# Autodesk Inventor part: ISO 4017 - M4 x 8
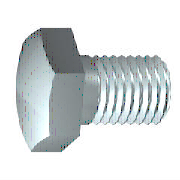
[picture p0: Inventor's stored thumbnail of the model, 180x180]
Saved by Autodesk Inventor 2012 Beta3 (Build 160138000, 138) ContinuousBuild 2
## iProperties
IsCustomPart: 0
Created: 2010-02
Part Number: ISO 4017 - M4 x 8
Material: Stainless Steel, 440C
Description: Hexagon head screws
Document SubType Name: Modeling
Standard: ISO 4017
Designer: Thom Tremblay
Standard Revision: Third edition 1999-08-15
Standards Organization: ISO
Language: en-US
Size Designation: M4 x 8
Categories: <MemberInstance><Categories><Category DisplayName="Fasteners" InternalName="e4da775c-781d-43d5-af7c-5136215cf5a6" Mnemonic="FSTN"><Category DisplayName="Bolts"
Density: 7.75 g/cm^3
Author: Thom Tremblay
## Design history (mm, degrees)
workplane "Work Plane1"
revolve "Body" stored, may be unused: angle "d12" = 90 deg
sketch "Sketch2"
  geometry: L1 (0, 4.041)-(3.5, 2.021); L2 (3.5, 2.021)-(3.5, -2.021); L3 (3.5, -2.021)-(0, -4.041); L4 (0, -4.041)-(-3.5, -2.021); L5 (-3.5, -2.021)-(-3.5, 2.021); L6 (-3.5, 2.021)-(0, 4.041); 2 further points
  constraints: 12 end point, 1 coincident, 1 vertical, 11 other
  dimensions: "d11" = 7 distance between parallel lines of L5 L2 (= SW)
extrude "Head" join sketch "Sketch2" distance "d3" = 2.4 (= KOH - SD); taper "d4" = 0 deg
revolve "Chamfer1" stored, may be unused: angle "d21" = 90 deg
body "Solid1"
feature "Thread" dims "d15" = 5.9 (= GEL), "d16" = 0
chamfer "Chamfer2" distance "d6" = 0.42941 (= -0.5 x SPD + 0.5 x GD); stored, may be unused: second distance "d7" = 0.42952 (computed from GUL), angle "d55" = 45 deg
sketch "Sketch1"
  geometry: L1 (0, 3.015)-(0, 2); L2 (2.1, 2)-(8, 2); L3 (8, 2)-(8, 0); L4 (8, 0)-(-0.4, 0); L5 (-2.08, 0)-(9.68, 0) reference; L6 (-0.4, 0)-(-0.4, 3.015); L7 (-0.4, 3.015)-(0, 3.015); L8 (2.1, 2)-(1.67, 2); L9 (1.67, 2)-(0, 2); L10 (0, -0.603)-(0, 3.618) reference
  constraints: 16 end point, 2 collinear, 2 perpendicular, 1 parallel
  dimensions: "d0" = 8 distance between parallel lines of L3 L1 (= NLG); "d1" = 5.9 distance from line of L2.start L3 (= GEL); "d2" = 4 diameter of L2 L4 (= GD); "d9" = 0.4001 distance between parallel lines of L6 L1 (computed from SD); "d10" = 6.03 diameter of L7 L4 (= SD2); "d13" = 0.42952 distance of L2.start L8.end (computed from GAL); "d14" = 4 diameter of L9 L4 (= BDM)
sketch "Sketch4"
  geometry: L1 (-2.8, 3.5)-(-2.8, 4.041); L2 (-2.8, 4.041)-(-2.487, 4.041); L3 (-2.487, 4.041)-(-2.8, 3.5); L4 (-3.28, 0)-(0.08, 0) reference; L5 (-0.4, 4.041)-(-2.8, 4.041) reference; L6 (-2.8, 2.021)-(-2.8, 4.041) reference
  constraints: 6 end point, 2 collinear, 1 perpendicular, 1 vertical
  dimensions: "d5" = 30 deg angle of L3 L1 (= ANG1); "d19" = 7 diameter of L1.start L4 (= SW0)
other parameters: "NLG" = 8 [user parameter; used in 1 equation term], "GD" = 4 (= NND) [user parameter; used in 2 equation terms], "BDM" = 4 (= NND) [user parameter; used in 1 equation term], "KOH" = 2.8 [user parameter; used in 1 equation term], "GEL" = 5.9 [user parameter; used in 2 equation terms], "SW" = 7 [user parameter; used in 2 equation terms], "SW0" = 7 (= SW) [user parameter; used in 1 equation term], "SPD" = 3.14117 (= NND - 1.2269 x PTC) [user parameter; used in 1 equation term], "SD2" = 6.03 [user parameter; used in 2 equation terms], "SD" = 0.4 [user parameter; used in 2 equation terms], "ANG1" = 30 deg [user parameter; used in 1 equation term], "GAL" = 0.42941 (= 0.61345 x PTC) [user parameter; used in 1 equation term], "GUL" = 0.42941 (= 0.61345 x PTC) [user parameter; used in 1 equation term], "d8" = 0, "RR" = 0.2 [user parameter], "d57" = 0, "d58" = 0, "TPU" = 14.28571 (computed from PTC) [user parameter], "GD1" = 3.14117 (= THREADDIA - 1.2269 x PTC) [user parameter], "THREADDIA" = 4 [user parameter; used in 1 equation term], "SDH" = 6.03 (= SD2) [user parameter], "SDHG" = 2.1 [user parameter], "TOA" = 30 deg [user parameter], "PTC" = 0.7 [user parameter; used in 5 equation terms], "NND" = 4 [user parameter; used in 3 equation terms], "E0" = 8.085 [user parameter]
